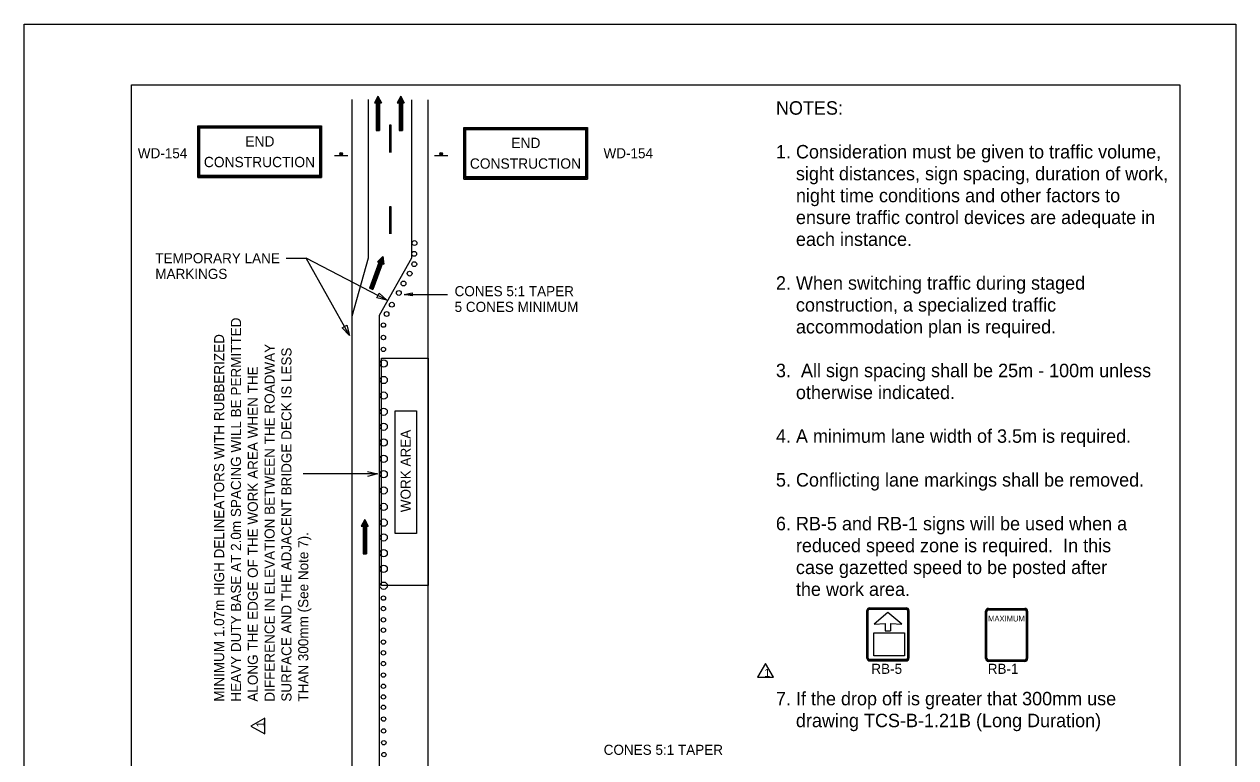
# Model space of a CAD drawing. Extents: x 1056 to 1280, y 240 to 519.
# Drawn here: x 1055.6 to 1271.6, y 388 to 518.8 of the extents above; entities that cross this region are included whole.
import ezdxf

# ---------------------------------------------------------------- set-up
doc = ezdxf.new("R2010")
doc.units = 0
for name, color, linetype in [('Level 10', 7, 'Continuous'), ('Level 17', 7, 'Continuous'), ('Level 36', 7, 'Continuous'), ('Level 44', 7, 'Continuous'), ('Level 5', 7, 'Continuous'), ('Level 60', 7, 'Continuous')]:
    doc.layers.add(name, color=color, linetype=linetype)

msp = doc.modelspace()

# ---------------------------------------------------------------- linework, layer by layer
at = {"layer": 'Level 10'}
for p, q in [((1063.51, 518.82), (1063.51, 518.82)), ((1118.62, 506.01), (1118, 504.78)), ((1118.39, 505.55), (1118.39, 499.88)), ((1118.46, 505.7), (1118.46, 499.88)), ((1118.54, 505.86), (1118.54, 499.88)), ((1118.62, 506.01), (1118.62, 499.88)), ((1118.62, 506.01), (1119.23, 504.78)), ((1118.69, 505.86), (1118.69, 499.88)), ((1118.77, 505.7), (1118.77, 499.88)), ((1118.85, 505.55), (1118.85, 499.88)), ((1122.68, 506.01), (1122.07, 504.78)), ((1122.45, 505.55), (1122.45, 499.88)), ((1122.53, 505.7), (1122.53, 499.88)), ((1122.61, 505.86), (1122.61, 499.88)), ((1122.68, 506.01), (1122.68, 499.88)), ((1122.68, 506.01), (1123.3, 504.78)), ((1122.76, 505.86), (1122.76, 499.88)), ((1122.84, 505.7), (1122.84, 499.88)), ((1122.91, 505.55), (1122.91, 499.88)), ((1114.04, 466.78), (1114.04, 505.37)), ((1116.95, 477.17), (1116.95, 505.37)), ((1118, 504.78), (1118.31, 504.78)), ((1118.08, 504.94), (1118.08, 504.78)), ((1118.16, 505.09), (1118.16, 504.78)), ((1118.23, 505.24), (1118.23, 504.78)), ((1118.31, 505.4), (1118.31, 499.88)), ((1118.31, 504.78), (1118.31, 499.88)), ((1118.92, 505.4), (1118.92, 499.88)), ((1118.92, 504.78), (1118.92, 499.88)), ((1118.92, 504.78), (1119.23, 504.78)), ((1119, 505.24), (1119, 504.78)), ((1119.08, 505.09), (1119.08, 504.78)), ((1119.15, 504.94), (1119.15, 504.78)), ((1122.07, 504.78), (1122.38, 504.78)), ((1122.15, 504.94), (1122.15, 504.78)), ((1122.22, 505.09), (1122.22, 504.78)), ((1122.3, 505.24), (1122.3, 504.78)), ((1122.38, 505.4), (1122.38, 499.88)), ((1122.38, 504.78), (1122.38, 499.88)), ((1122.99, 505.4), (1122.99, 499.88)), ((1122.99, 504.78), (1122.99, 499.88)), ((1122.99, 504.78), (1123.3, 504.78)), ((1123.07, 505.24), (1123.07, 504.78)), ((1123.14, 505.09), (1123.14, 504.78)), ((1123.22, 504.94), (1123.22, 504.78)), ((1124.69, 477.17), (1124.69, 505.34)), ((1127.59, 459.29), (1127.59, 505.34)), ((1118.31, 499.88), (1118.92, 499.88)), ((1120.7, 500.81), (1120.7, 495.97)), ((1121, 500.81), (1120.7, 500.81)), ((1121, 495.97), (1121, 500.81)), ((1122.38, 499.88), (1122.99, 499.88)), ((1120.7, 486.29), (1120.7, 481.45)), ((1121, 486.29), (1120.7, 486.29)), ((1121, 481.45), (1121, 486.29)), ((1119.52, 477.4), (1117.42, 471.63)), ((1119.52, 477.4), (1118.52, 476.46)), ((1119.52, 477.4), (1119.67, 476.04)), ((1102.25, 477.11), (1105.85, 477.11)), ((1113.54, 463.35), (1105.85, 477.11)), ((1120.21, 469.62), (1105.85, 477.11)), ((1114.04, 466.78), (1116.95, 477.17)), ((1119.02, 476.93), (1117.13, 471.74)), ((1118.81, 476.35), (1117.13, 471.74)), ((1119.14, 477.04), (1117.2, 471.71)), ((1119.27, 477.16), (1117.28, 471.69)), ((1119.39, 477.28), (1117.35, 471.66)), ((1119.54, 477.23), (1117.49, 471.61)), ((1119.56, 477.06), (1117.56, 471.58)), ((1119.58, 476.89), (1117.64, 471.56)), ((1119.6, 476.72), (1117.71, 471.53)), ((1119.39, 476.14), (1117.71, 471.53)), ((1118.52, 476.46), (1118.81, 476.35)), ((1118.65, 476.57), (1118.6, 476.43)), ((1118.77, 476.69), (1118.67, 476.4)), ((1118.9, 476.81), (1118.74, 476.38)), ((1118.93, 466.95), (1124.69, 477.17)), ((1119.39, 476.14), (1119.67, 476.04)), ((1119.62, 476.55), (1119.46, 476.12)), ((1119.64, 476.38), (1119.53, 476.09)), ((1119.66, 476.21), (1119.6, 476.06)), ((1117.13, 471.74), (1117.71, 471.53)), ((1114.04, 459.29), (1114.04, 467.1)), ((1114.04, 431.5), (1114.04, 459.29)), ((1127.59, 418.74), (1127.59, 459.29)), ((1118.56, 438.64), (1105.32, 438.64)), ((1114.04, 384.85), (1114.04, 432.01)), ((1116.27, 430.54), (1115.66, 429.31)), ((1115.97, 429.93), (1115.97, 424.4)), ((1116.04, 430.08), (1116.04, 424.4)), ((1116.12, 430.23), (1116.12, 424.4)), ((1116.2, 430.38), (1116.2, 424.4)), ((1116.27, 430.54), (1116.27, 424.4)), ((1116.27, 430.54), (1116.88, 429.31)), ((1116.35, 430.38), (1116.35, 424.4)), ((1116.42, 430.23), (1116.42, 424.4)), ((1116.5, 430.08), (1116.5, 424.4)), ((1116.58, 429.93), (1116.58, 424.4)), ((1127.59, 329.09), (1127.59, 431.5)), ((1115.66, 429.31), (1115.97, 429.31)), ((1115.74, 429.46), (1115.74, 429.31)), ((1115.81, 429.62), (1115.81, 429.31)), ((1115.89, 429.77), (1115.89, 429.31)), ((1115.97, 429.31), (1115.97, 424.4)), ((1116.58, 429.31), (1116.58, 424.4)), ((1116.58, 429.31), (1116.88, 429.31)), ((1116.66, 429.77), (1116.66, 429.31)), ((1116.73, 429.62), (1116.73, 429.31)), ((1116.81, 429.46), (1116.81, 429.31)), ((1115.97, 424.4), (1116.58, 424.4)), ((1127.59, 418.74), (1119.28, 418.74)), ((1114.04, 384.85), (1114.04, 397.84))]:
    msp.add_line(p, q, dxfattribs=at)
for points in [[(1055.56, 518.82), (1271.56, 518.82), (1271.56, 239.82), (1055.56, 239.82)], [(1074.69, 508.01), (1261.56, 508.01), (1261.56, 250.63), (1074.69, 250.63)], [(1118.82, 470.85), (1120.21, 469.62), (1118.41, 470.05)], [(1113.06, 465.14), (1113.54, 463.35), (1112.27, 464.7)], [(1119.28, 459.29), (1127.59, 459.29), (1127.59, 418.74), (1119.28, 418.74)], [(1121.7, 449.87), (1125.47, 449.87), (1125.47, 428.04), (1121.7, 428.04)]]:
    msp.add_lwpolyline(points, close=True, dxfattribs=at)
msp.add_lwpolyline([(1116.76, 439.09), (1118.56, 438.64), (1116.76, 438.19)], dxfattribs=at)
for centre, radius in [((1125.14, 479.8), 0.431), ((1125.09, 477.88), 0.431), ((1125.1, 476.04), 0.431), ((1124.27, 474.36), 0.431), ((1122.34, 470.91), 0.431), ((1123.19, 472.59), 0.431), ((1121.11, 468.81), 0.431), ((1120.17, 467.15), 0.431), ((1119.64, 458.34), 0.652), ((1119.64, 455.39), 0.652), ((1119.64, 452.61), 0.652), ((1119.64, 449.73), 0.652), ((1119.64, 447.06), 0.652), ((1119.64, 444.25), 0.652), ((1119.64, 441.32), 0.652), ((1119.64, 438.61), 0.652), ((1119.64, 435.71), 0.652), ((1119.64, 432.76), 0.652), ((1119.64, 429.96), 0.652), ((1119.64, 427.33), 0.652), ((1119.64, 424.51), 0.652), ((1119.64, 421.71), 0.652), ((1119.64, 418.72), 0.652)]:
    msp.add_circle(centre, radius, dxfattribs=at)
at = {"layer": 'Level 17'}
for p, q in [((1086.51, 491.49), (1108.59, 491.49)), ((1133.93, 491.22), (1156.01, 491.22)), ((1206.29, 414.77), (1212.79, 414.77)), ((1206.29, 414.77), (1206.29, 414.77)), ((1205.79, 405.79), (1205.79, 414.27)), ((1205.92, 405.79), (1205.92, 414.27)), ((1206.04, 405.79), (1206.04, 414.27)), ((1206.29, 414.64), (1212.79, 414.64)), ((1206.29, 414.64), (1206.29, 414.64)), ((1206.29, 414.52), (1212.79, 414.52)), ((1206.29, 414.52), (1206.29, 414.52)), ((1213.04, 414.27), (1213.04, 405.79)), ((1213.17, 414.27), (1213.17, 405.79)), ((1213.29, 414.27), (1213.29, 405.79)), ((1226.95, 405.71), (1226.95, 414.18)), ((1227.08, 405.71), (1227.08, 414.18)), ((1227.2, 405.71), (1227.2, 414.18)), ((1227.22, 414.58), (1227.22, 414.58)), ((1227.34, 414.63), (1227.34, 414.63)), ((1227.45, 414.68), (1233.95, 414.68)), ((1227.45, 414.68), (1227.45, 414.68)), ((1227.45, 414.55), (1233.95, 414.55)), ((1227.45, 414.43), (1233.95, 414.43)), ((1234.2, 414.18), (1234.2, 405.71)), ((1234.33, 414.18), (1234.33, 405.71)), ((1234.45, 414.18), (1234.45, 405.71)), ((1212.79, 405.54), (1206.29, 405.54)), ((1212.79, 405.42), (1206.29, 405.42)), ((1212.79, 405.29), (1206.29, 405.29)), ((1233.95, 405.46), (1227.45, 405.46)), ((1233.95, 405.33), (1227.45, 405.33)), ((1233.95, 405.21), (1227.45, 405.21))]:
    msp.add_line(p, q, dxfattribs=at)
for points in [[(1086.51, 500.69), (1108.59, 500.69), (1108.59, 491.49), (1086.51, 491.49)], [(1086.7, 500.51), (1108.41, 500.51), (1108.41, 491.68), (1086.7, 491.68)], [(1086.88, 500.32), (1108.23, 500.32), (1108.23, 491.86), (1086.88, 491.86)], [(1133.93, 500.42), (1156.01, 500.42), (1156.01, 491.22), (1133.93, 491.22)], [(1134.12, 500.24), (1155.83, 500.24), (1155.83, 491.41), (1134.12, 491.41)], [(1134.3, 500.05), (1155.65, 500.05), (1155.65, 491.59), (1134.3, 491.59)], [(1207.03, 410.3), (1212.49, 410.3), (1212.49, 406.2), (1207.03, 406.2)]]:
    msp.add_lwpolyline(points, close=True, dxfattribs=at)
for centre, radius, start, end in [((1206.29, 414.27), 0.501, 90, 180), ((1212.79, 414.27), 0.501, 0, 90), ((1206.29, 414.27), 0.376, 90, 180), ((1206.29, 414.27), 0.251, 90, 180), ((1212.79, 414.27), 0.376, 0, 90), ((1212.79, 414.27), 0.251, 0, 90), ((1227.45, 414.18), 0.501, 90, 180), ((1227.45, 414.18), 0.376, 90, 180), ((1227.45, 414.18), 0.251, 90, 180), ((1233.95, 414.18), 0.501, 0, 90), ((1233.95, 414.18), 0.376, 0, 90), ((1233.95, 414.18), 0.251, 0, 90), ((1206.29, 405.8), 0.501, 180, 270), ((1206.29, 405.8), 0.376, 180, 270), ((1206.29, 405.8), 0.251, 180, 270), ((1212.79, 405.8), 0.501, 270, 0), ((1212.79, 405.8), 0.376, 270, 0), ((1212.79, 405.8), 0.251, 270, 0), ((1227.45, 405.71), 0.501, 180, 270), ((1227.45, 405.71), 0.376, 180, 270), ((1227.45, 405.71), 0.251, 180, 270), ((1233.95, 405.71), 0.501, 270, 0), ((1233.95, 405.71), 0.376, 270, 0), ((1233.95, 405.71), 0.251, 270, 0)]:
    msp.add_arc(centre, radius, start, end, dxfattribs=at)
at = {"layer": 'Level 36'}
for p, q in [((1209.54, 413.96), (1207.07, 411.87)), ((1212.01, 411.87), (1209.54, 413.96)), ((1207.07, 411.87), (1209.04, 411.98)), ((1209.04, 411.98), (1209.04, 410.66)), ((1209.04, 410.66), (1210.03, 410.66)), ((1210.04, 410.66), (1210.04, 411.98)), ((1210.04, 411.98), (1212.01, 411.87))]:
    msp.add_line(p, q, dxfattribs=at)
at = {"layer": 'Level 44'}
for p, q in [((1110.88, 495.44), (1113.28, 495.44)), ((1128.69, 495.44), (1131.09, 495.44))]:
    msp.add_line(p, q, dxfattribs=at)
for centre, radius in [((1112.08, 495.71), 0.24), ((1112.08, 495.71), 0.12), ((1129.9, 495.71), 0.24), ((1129.9, 495.71), 0.12)]:
    msp.add_circle(centre, radius, dxfattribs=at)
at = {"layer": 'Level 5'}
for p, q in [((1123.3, 470.65), (1131.02, 470.65)), ((1118.93, 459.29), (1118.93, 466.95)), ((1118.93, 382.82), (1118.93, 459.29))]:
    msp.add_line(p, q, dxfattribs=at)
msp.add_lwpolyline([(1124.74, 470.38), (1123.3, 470.65), (1124.74, 470.92)], close=True, dxfattribs=at)
for centre in [(1119.59, 465.17), (1119.59, 462.97), (1119.59, 460.84), (1119.59, 416.5), (1119.59, 414.64), (1119.59, 412.63), (1119.59, 410.79), (1119.59, 408.67), (1119.59, 406.75), (1119.59, 404.82), (1119.59, 402.78), (1119.59, 400.78), (1119.59, 398.89), (1119.59, 397.05), (1119.62, 394.94), (1119.64, 392.83), (1119.67, 390.72), (1119.69, 388.61)]:
    msp.add_circle(centre, 0.391, dxfattribs=at)
at = {"layer": 'Level 60'}
for points in [[(1187.71, 404.86), (1186.29, 402.39), (1189.13, 402.39)], [(1095.99, 393.7), (1098.46, 392.28), (1098.46, 395.12)]]:
    msp.add_lwpolyline(points, close=True, dxfattribs=at)

# ---------------------------------------------------------------- texts
at = {"layer": 'Level 10'}
for s, height, p in [('NOTES:', 2.4, (1189.58, 502.69)), ('1. Consideration must be given to traffic volume,', 2.4, (1189.58, 494.89)), ('WD-154', 1.8, (1075.81, 494.92)), ('WD-154', 1.8, (1158.84, 494.92)), ('    sight distances, sign spacing, duration of work,', 2.4, (1189.58, 490.99)), ('    night time conditions and other factors to', 2.4, (1189.58, 487.09)), ('    ensure traffic control devices are adequate in', 2.4, (1189.58, 483.19)), ('    each instance.', 2.4, (1189.58, 479.29)), ('TEMPORARY LANE', 1.8, (1078.93, 476.2)), ('MARKINGS', 1.8, (1078.93, 473.41)), ('2. When switching traffic during staged ', 2.4, (1189.58, 471.49)), ('CONES 5:1 TAPER', 1.8, (1132.29, 470.33)), ('5 CONES MINIMUM', 1.8, (1132.29, 467.53)), ('    construction, a specialized traffic ', 2.4, (1189.58, 467.59)), ('    accommodation plan is required.', 2.4, (1189.58, 463.69)), ('3.  All sign spacing shall be 25m - 100m unless', 2.4, (1189.58, 455.89)), ('    otherwise indicated. ', 2.4, (1189.58, 451.99)), ('4. A minimum lane width of 3.5m is required.', 2.4, (1189.58, 444.19)), ('5. Conflicting lane markings shall be removed.', 2.4, (1189.58, 436.39)), ('6. RB-5 and RB-1 signs will be used when a ', 2.4, (1189.58, 428.59)), ('    reduced speed zone is required.  In this ', 2.4, (1189.58, 424.69)), ('    case gazetted speed to be posted after ', 2.4, (1189.58, 420.79)), ('    the work area.', 2.4, (1189.58, 416.89)), ('7. If the drop off is greater that 300mm use ', 2.4, (1189.58, 397.39)), ('    drawing TCS-B-1.21B (Long Duration)', 2.4, (1189.58, 393.49)), ('CONES 5:1 TAPER', 1.8, (1158.87, 388.56))]:
    msp.add_text(s, height=height, dxfattribs=at).set_placement(p)
for s, p in [('HEAVY DUTY BASE AT 2.0m SPACING WILL BE PERMITTED', (1094.21, 398.04)), ('MINIMUM 1.07m HIGH DELINEATORS WITH RUBBERIZED', (1091.21, 398.04)), ('DIFFERENCE IN ELEVATION BETWEEN THE ROADWAY', (1100.21, 398.04)), ('SURFACE AND THE ADJACENT BRIDGE DECK IS LESS', (1103.21, 398.04)), ('ALONG THE EDGE OF THE WORK AREA WHEN THE', (1097.21, 398.04)), ('WORK AREA', (1124.46, 431.81)), ('THAN 300mm (See Note 7).', (1106.21, 398.04))]:
    msp.add_text(s, height=1.8, rotation=90, dxfattribs=at).set_placement(p)
at = {"layer": 'Level 17'}
for s, p in [('END', (1094.98, 497.01)), ('END', (1142.4, 496.74)), ('CONSTRUCTION', (1087.59, 493.33)), ('CONSTRUCTION', (1135.01, 493.06))]:
    msp.add_text(s, height=1.84, rotation=360, dxfattribs=at).set_placement(p)
for s, height, p in [('MAXIMUM', 1.012, (1227.41, 412.34)), ('RB-5', 1.8, (1206.59, 403)), ('RB-1', 1.8, (1227.34, 403))]:
    msp.add_text(s, height=height, dxfattribs=at).set_placement(p)
at = {"layer": 'Level 60'}
for rotation, p in [(360, (1187.48, 402.44)), (90, (1098.41, 393.47))]:
    msp.add_text('1', height=1.45, rotation=rotation, dxfattribs=at).set_placement(p)

doc.saveas('drawing.dxf')
